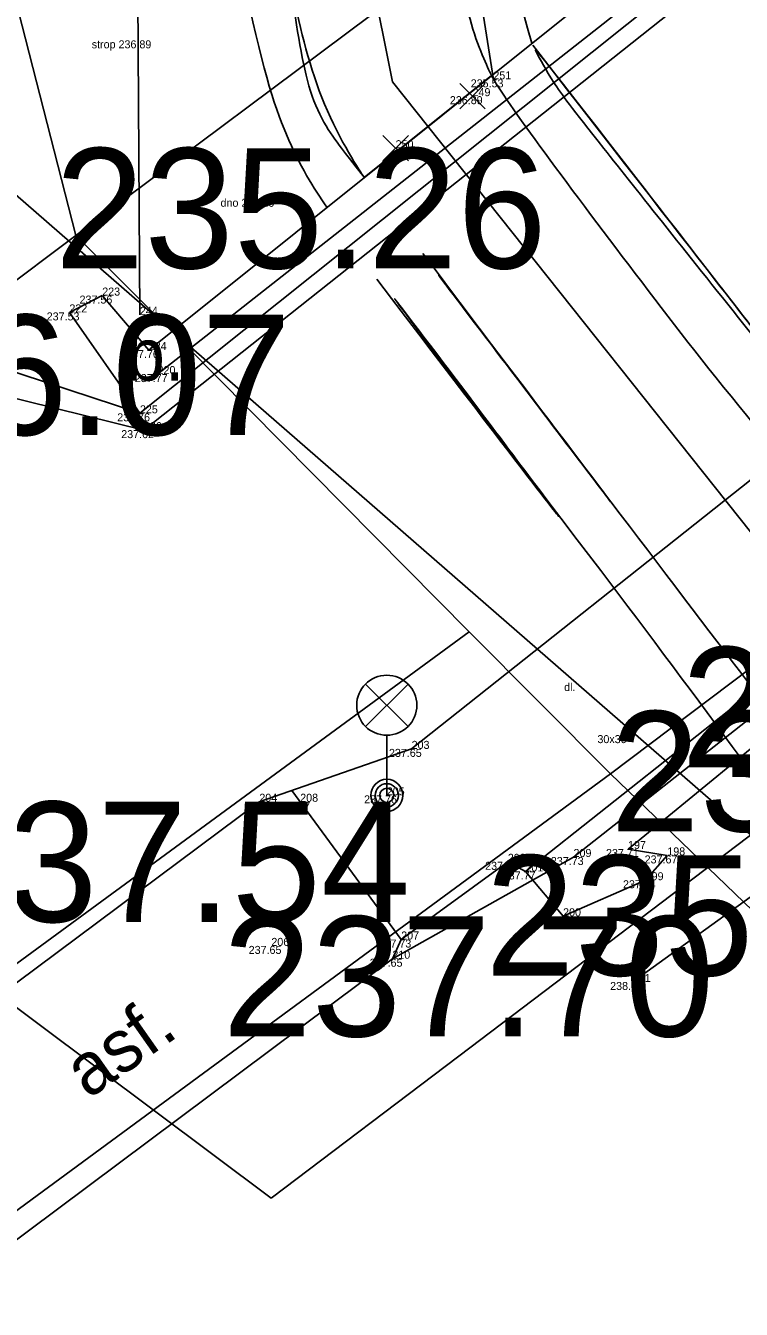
# Model space of a CAD drawing. Extents: x -555757 to -553364, y -1100723 to -1096439.
# Drawn here: x -554318.17 to -554309.25, y -1100527.75 to -1100511.72 of the extents above; entities that cross this region are included whole.
import ezdxf

# ---------------------------------------------------------------- set-up
doc = ezdxf.new("R2010")
doc.units = 0
for name, color, linetype in [('00_NÁVRH - 0.18 mm', 7, 'Continuous'), ('00_NÁVRH - 0.35 mm', 7, 'Continuous'), ('01_HLADINA', 7, 'Continuous'), ('05_SÍTĚ - plynovod STL', 7, 'Continuous'), ('05_SÍTĚ - vedení VN - nadzemní', 7, 'Continuous'), ('ELEKTRO', 7, 'Continuous'), ('Geodet. výšky - netisknuté', 7, 'Continuous'), ('HRANA$SVAHU', 7, 'Continuous'), ('HRANICE$PARCELY', 7, 'Continuous'), ('OSA$KOLEJI', 7, 'Continuous'), ('PLOTY', 7, 'Continuous'), ('POPIS', 7, 'Continuous'), ('POPIS$POVRCHU', 7, 'Continuous'), ('ROZHRANI', 7, 'Continuous'), ('SLUCKOV$$C$RA', 7, 'Continuous'), ('SVODIDLA', 7, 'Continuous'), ('VOZOVKA', 7, 'Continuous'), ('VYSKA_PODR_BOD', 7, 'Continuous')]:
    doc.layers.add(name, color=color, linetype=linetype)

# ---------------------------------------------------------------- blocks, each defined once
blk = doc.blocks.new('POINT_DISPLAY')
blk.add_line((0, 0), (0, 0))
blk = doc.blocks.new('6$560')
at = {"layer": 'ELEKTRO'}
for p, q in [((-0.265, 0.86), (0.265, 1.39)), ((-0.265, 1.39), (0.265, 0.86)), ((0, 0.75), (0, 0))]:
    blk.add_line(p, q, dxfattribs=at)
for centre, radius in [((0, 1.125), 0.375), ((0, 0), 0.2), ((0, 0), 0.145), ((0, 0), 0.0876)]:
    blk.add_circle(centre, radius, dxfattribs=at)
blk = doc.blocks.new('BOD')
at = {"layer": 'POPIS'}
for p, q in [((-0.283, -0.283), (0.283, 0.283)), ((-0.283, 0.283), (0.283, -0.283))]:
    blk.add_line(p, q, dxfattribs=at)

msp = doc.modelspace()

# ---------------------------------------------------------------- linework, layer by layer
at = {"layer": '00_NÁVRH - 0.18 mm'}
msp.add_lwpolyline([(-554230.466, -1100601.206), (-554249.164, -1100583.038), (-554263.07, -1100566.98), (-554269.426, -1100554.136), (-554270.586, -1100551.573), (-554271.594, -1100550.189), (-554284.219, -1100538.005), (-554306.94, -1100520.848), (-554308.081, -1100519.365), (-554313.597, -1100512.423), (-554314.94, -1100505.715), (-554315.308, -1100495.76), (-554315.472, -1100482.811), (-554315.568, -1100470.17)], dxfattribs=at)
for points in [[(-554314.417, -1100513.988), (-554314.582, -1100513.749), (-554314.935, -1100513.181), (-554315.384, -1100511.726), (-554316.281, -1100506.604), (-554316.377, -1100505.57), (-554316.456, -1100503.941), (-554316.566, -1100500.746), (-554316.659, -1100497.74), (-554316.762, -1100493.317), (-554316.913, -1100488.501), (-554317.002, -1100484.644), (-554317.257, -1100477.919), (-554317.382, -1100473.141), (-554317.442, -1100469.848), (-554317.606, -1100466.831), (-554317.722, -1100464.81), (-554317.805, -1100463.233), (-554317.759, -1100462.426), (-554316.795, -1100460.405), (-554314.574, -1100457.619), (-554311.478, -1100453.9), (-554309.939, -1100451.947), (-554307.949, -1100449.799), (-554306.455, -1100448.289), (-554306.121, -1100447.993), (-554314.5, -1100513.869), (-554306.291, -1100448.139)], [(-554311.86, -1100511.938), (-554312.434, -1100509.94), (-554313.024, -1100507.015), (-554313.36, -1100504.824), (-554313.477, -1100502.343), (-554313.592, -1100499.092), (-554313.64, -1100493.221), (-554313.549, -1100489.959), (-554313.549, -1100484.214), (-554313.549, -1100477.597), (-554313.714, -1100471.542), (-554313.882, -1100467.25), (-554313.923, -1100465.45), (-554313.767, -1100464.089), (-554312.685, -1100462.214), (-554309.214, -1100458.206), (-554306.593, -1100455.182), (-554303.675, -1100452.188), (-554303.213, -1100451.814), (-554312.278, -1100510.987), (-554303.447, -1100451.997)]]:
    msp.add_open_spline(points, degree=3, dxfattribs=at)
at = {"layer": '00_NÁVRH - 0.35 mm'}
for points in [[(-554313.952, -1100513.615), (-554313.958, -1100513.608), (-554314.479, -1100512.835), (-554314.851, -1100511.368), (-554315.085, -1100510.042), (-554315.469, -1100507.851), (-554315.769, -1100506.129), (-554315.816, -1100505.705), (-554315.847, -1100504.963), (-554315.974, -1100501.578), (-554316.005, -1100498.962), (-554316.1, -1100495.84), (-554316.131, -1100492.846), (-554316.249, -1100488.998), (-554316.401, -1100481.419), (-554316.527, -1100473.073), (-554316.625, -1100469.789), (-554316.956, -1100464.389), (-554316.87, -1100462.539), (-554316.374, -1100461.233), (-554314.939, -1100459.29), (-554312.44, -1100456.572), (-554309.696, -1100453.384), (-554307.571, -1100451.07), (-554306.062, -1100449.51), (-554305.473, -1100448.922), (-554305.437, -1100448.893), (-554313.955, -1100513.612), (-554305.455, -1100448.907)], [(-554312.363, -1100512.342), (-554312.368, -1100512.333), (-554312.623, -1100511.834), (-554312.839, -1100510.653), (-554313.388, -1100508.394), (-554314.085, -1100505.395), (-554314.208, -1100501.825), (-554314.497, -1100495.645), (-554314.475, -1100486.499), (-554314.473, -1100475.881), (-554314.602, -1100468.426), (-554314.862, -1100464.792), (-554314.485, -1100462.214), (-554311.756, -1100459.401), (-554309.164, -1100456.443), (-554306.736, -1100453.248), (-554305.198, -1100451.285), (-554304.284, -1100450.563), (-554304.209, -1100450.506)], [(-554306.575, -1100518.653), (-554307.669, -1100517.377), (-554309.181, -1100515.497), (-554311.244, -1100512.902), (-554311.609, -1100512.418), (-554311.836, -1100511.991), (-554311.86, -1100511.938), (-554307.14, -1100518.031), (-554311.848, -1100511.965)], [(-554307.026, -1100519.023), (-554308.753, -1100517.178), (-554310.495, -1100514.937), (-554312.216, -1100512.627), (-554312.363, -1100512.342)], [(-554308.761, -1100520.444), (-554309.342, -1100519.683), (-554312.501, -1100515.521), (-554313.952, -1100513.615), (-554309.055, -1100520.067), (-554313.221, -1100514.564)], [(-554309.262, -1100520.855), (-554310.316, -1100519.408), (-554313.123, -1100515.755), (-554314.417, -1100513.988), (-554309.793, -1100520.135), (-554313.792, -1100514.887)]]:
    msp.add_open_spline(points, degree=3, dxfattribs=at)
at = {"layer": '01_HLADINA'}
msp.add_line((-554312.363, -1100512.342), (-554313.952, -1100513.615), dxfattribs=at)
for points in [[(-554313.952, -1100513.615), (-554313.954, -1100513.613), (-554314.147, -1100513.362), (-554314.657, -1100512.705), (-554314.831, -1100511.412), (-554315.142, -1100509.759), (-554315.428, -1100508.004), (-554315.72, -1100506.567), (-554315.834, -1100505.6), (-554315.861, -1100504.081), (-554316.002, -1100501.836), (-554315.982, -1100498.792), (-554316.127, -1100495.884), (-554316.108, -1100492.56), (-554316.315, -1100487.756), (-554316.405, -1100481.162), (-554316.489, -1100474.763), (-554316.595, -1100469.817), (-554316.756, -1100467.676), (-554316.828, -1100466.617)], [(-554314.719, -1100466.971), (-554314.586, -1100469.377), (-554314.473, -1100476.033), (-554314.475, -1100486.499), (-554314.497, -1100495.645), (-554314.208, -1100501.825), (-554314.085, -1100505.395), (-554313.388, -1100508.394), (-554312.839, -1100510.653), (-554312.623, -1100511.834), (-554312.368, -1100512.333), (-554312.363, -1100512.342)]]:
    msp.add_open_spline(points, degree=3, dxfattribs=at)
at = {"layer": '05_SÍTĚ - plynovod STL'}
for points in [[(-554315.112, -1100526.36), (-554312.77, -1100524.585), (-554300.767, -1100515.483), (-554300.424, -1100515.223)], [(-554315.112, -1100526.36), (-554320.923, -1100522.01), (-554329.36, -1100528.11), (-554330.095, -1100528.467), (-554330.215, -1100528.551), (-554331.438, -1100529.419), (-554333.271, -1100530.719)]]:
    msp.add_lwpolyline(points, dxfattribs=at)
at = {"layer": '05_SÍTĚ - vedení VN - nadzemní'}
msp.add_lwpolyline([(-554324.546, -1100507.473), (-554320.113, -1100512.256), (-554293.478, -1100535.466), (-554257.717, -1100565.776), (-554219.756, -1100599.256), (-554187.611, -1100626.856)], dxfattribs=at)
at = {"layer": 'HRANA$SVAHU'}
msp.add_line((-554312.34, -1100512.39), (-554314.17, -1100500.56), dxfattribs=at)
at = {"layer": 'HRANICE$PARCELY'}
for p, q in [((-554317.55, -1100514.34), (-554320.29, -1100503.59)), ((-554317.55, -1100514.34), (-554310.54, -1100509.1)), ((-554310.88, -1100521.06), (-554329.35, -1100534.66)), ((-554293.88, -1100537.46), (-554310.88, -1100521.06))]:
    msp.add_line(p, q, dxfattribs=at)
msp.add_lwpolyline([(-554310.88, -1100521.06), (-554312.64, -1100519.29), (-554316.17, -1100515.72), (-554317.55, -1100514.34)], dxfattribs=at)
at = {"layer": 'PLOTY'}
for p, q in [((-554313.6, -1100523.37), (-554311.34, -1100522.1)), ((-554319.12, -1100527.5), (-554313.6, -1100523.37))]:
    msp.add_line(p, q, dxfattribs=at)
at = {"layer": 'POPIS'}
msp.add_line((-554310.6, -1100523.66), (-554300.06, -1100516.02), dxfattribs=at)
at = {"layer": 'ROZHRANI'}
for p, q in [((-554316.8, -1100507.63), (-554316.75, -1100515.33)), ((-554310.04, -1100510.48), (-554316.64, -1100515.77)), ((-554316.75, -1100516.56), (-554309.32, -1100510.62)), ((-554317.22, -1100515.09), (-554317.63, -1100515.3)), ((-554316.64, -1100515.77), (-554317.22, -1100515.09)), ((-554317.63, -1100515.3), (-554316.75, -1100516.56)), ((-554316.75, -1100516.56), (-554318.66, -1100515.93)), ((-554311.94, -1100522.28), (-554304.494, -1100516.378)), ((-554310.66, -1100522), (-554304.74, -1100517.15)), ((-554313.49, -1100523.13), (-554314.853, -1100521.269)), ((-554310.17, -1100522.08), (-554310.66, -1100522)), ((-554313.49, -1100523.13), (-554312.16, -1100522.16)), ((-554312.16, -1100522.16), (-554311.94, -1100522.28)), ((-554310.44, -1100522.39), (-554310.17, -1100522.08)), ((-554311.94, -1100522.28), (-554311.47, -1100522.84)), ((-554311.47, -1100522.84), (-554310.44, -1100522.39)), ((-554313.6, -1100523.37), (-554313.49, -1100523.13))]:
    msp.add_line(p, q, dxfattribs=at)
at = {"layer": 'SLUCKOV$$C$RA'}
for p, q in [((-554321.34, -1100517.19), (-554317.55, -1100514.34)), ((-554310.88, -1100521.06), (-554304.43, -1100516.2)), ((-554312.64, -1100519.29), (-554366.85, -1100559.01))]:
    msp.add_line(p, q, dxfattribs=at)
at = {"layer": 'SVODIDLA'}
for p, q in [((-554306.71, -1100508.34), (-554316.53, -1100516.07)), ((-554311.34, -1100522.1), (-554301.52, -1100514.37))]:
    msp.add_line(p, q, dxfattribs=at)
at = {"layer": 'VOZOVKA'}
for p, q in [((-554306.21, -1100508.44), (-554316.7, -1100516.77)), ((-554313.36, -1100520.75), (-554302.81, -1100512.37)), ((-554316.7, -1100516.77), (-554318.98, -1100516.21)), ((-554315.26, -1100521.41), (-554313.36, -1100520.75)), ((-554320.52, -1100525.33), (-554315.26, -1100521.41))]:
    msp.add_line(p, q, dxfattribs=at)

# ---------------------------------------------------------------- block references
at = {"layer": 'ELEKTRO'}
msp.add_blockref('6$560', (-554313.67, -1100521.33), dxfattribs=at)
at = {"layer": 'POPIS', "xscale": 0.5624965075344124, "yscale": 0.5624965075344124}
for p in [(-554312.6, -1100512.6), (-554313.56, -1100513.25)]:
    msp.add_blockref('BOD', p, dxfattribs=at)
at = {"layer": 'ROZHRANI'}
for p in [(-554312.34, -1100512.39), (-554312.6, -1100512.6), (-554313.56, -1100513.25), (-554317.22, -1100515.09), (-554317.63, -1100515.3), (-554316.75, -1100515.33), (-554316.64, -1100515.77), (-554316.53, -1100516.07), (-554316.75, -1100516.56), (-554316.7, -1100516.77), (-554313.36, -1100520.75), (-554315.26, -1100521.41), (-554314.75, -1100521.41), (-554313.67, -1100521.33), (-554310.66, -1100522), (-554312.16, -1100522.16), (-554311.34, -1100522.1), (-554310.17, -1100522.08), (-554311.94, -1100522.28), (-554310.44, -1100522.39), (-554311.47, -1100522.84), (-554313.49, -1100523.13), (-554315.11, -1100523.21), (-554313.6, -1100523.37), (-554310.6, -1100523.66)]:
    msp.add_blockref('POINT_DISPLAY', p, dxfattribs=at)

# ---------------------------------------------------------------- texts
at = {"layer": 'Geodet. výšky - netisknuté'}
for s, p in [('strop 236.89', (-554317.351, -1100512.003)), ('235.53', (-554312.623, -1100512.49)), ('236.89', (-554312.883, -1100512.7)), ('dno 235.26', (-554315.744, -1100513.981)), ('237.56', (-554317.503, -1100515.19)), ('237.53', (-554317.913, -1100515.4)), ('237.76', (-554316.923, -1100515.87)), ('237.77', (-554316.813, -1100516.17)), ('237.76', (-554317.033, -1100516.66)), ('237.62', (-554316.983, -1100516.87)), ('dl.', (-554311.457, -1100520.028)), ('30x30', (-554311.042, -1100520.678)), ('237.65', (-554313.643, -1100520.85)), ('237.67', (-554315.033, -1100521.51)), ('237.76', (-554313.953, -1100521.43)), ('237.71', (-554310.935, -1100522.1)), ('237.78', (-554312.443, -1100522.26)), ('237.73', (-554311.623, -1100522.2)), ('237.67', (-554310.453, -1100522.18)), ('237.77', (-554312.223, -1100522.38)), ('237.64', (-554310.723, -1100522.49)), ('237.73', (-554313.773, -1100523.23)), ('237.65', (-554315.393, -1100523.31)), ('237.65', (-554313.883, -1100523.47)), ('238.43', (-554310.883, -1100523.76))]:
    msp.add_text(s, height=0.1, dxfattribs=at).set_placement(p)
at = {"layer": 'OSA$KOLEJI'}
for s, p in [('251', (-554312.34, -1100512.39)), ('249', (-554312.6, -1100512.6)), ('250', (-554313.56, -1100513.25)), ('223', (-554317.22, -1100515.09)), ('222', (-554317.63, -1100515.3)), ('244', (-554316.75, -1100515.33)), ('224', (-554316.64, -1100515.77)), ('220', (-554316.53, -1100516.07)), ('225', (-554316.75, -1100516.56)), ('226', (-554316.7, -1100516.77)), ('203', (-554313.36, -1100520.75)), ('205', (-554313.67, -1100521.33)), ('204', (-554315.26, -1100521.41)), ('208', (-554314.75, -1100521.41)), ('197', (-554310.66, -1100522)), ('202', (-554312.16, -1100522.16)), ('209', (-554311.34, -1100522.1)), ('198', (-554310.17, -1100522.08)), ('201', (-554311.94, -1100522.28)), ('199', (-554310.44, -1100522.39)), ('200', (-554311.47, -1100522.84)), ('207', (-554313.49, -1100523.13)), ('206', (-554315.11, -1100523.21)), ('210', (-554313.6, -1100523.37)), ('221', (-554310.6, -1100523.66))]:
    msp.add_text(s, height=0.1, dxfattribs=at).set_placement(p)
at = {"layer": 'POPIS$POVRCHU'}
msp.add_text('b.', height=0.65, dxfattribs=at).set_placement((-554316.922, -1100516.151))
msp.add_text('asf.', height=0.65, rotation=35.04, dxfattribs=at).set_placement((-554317.395, -1100525.13))
at = {"layer": 'VYSKA_PODR_BOD'}
for s, p in [('235.26', (-554317.81, -1100514.75)), ('236.07', (-554321, -1100516.83)), ('235.51', (-554309.995, -1100520.98)), ('235.20', (-554310.88, -1100521.78)), ('237.54', (-554319.51, -1100522.91)), ('235.46', (-554312.44, -1100523.58)), ('237.70', (-554315.72, -1100524.34))]:
    msp.add_text(s, height=1.5, dxfattribs=at).set_placement(p)

doc.saveas('drawing.dxf')
